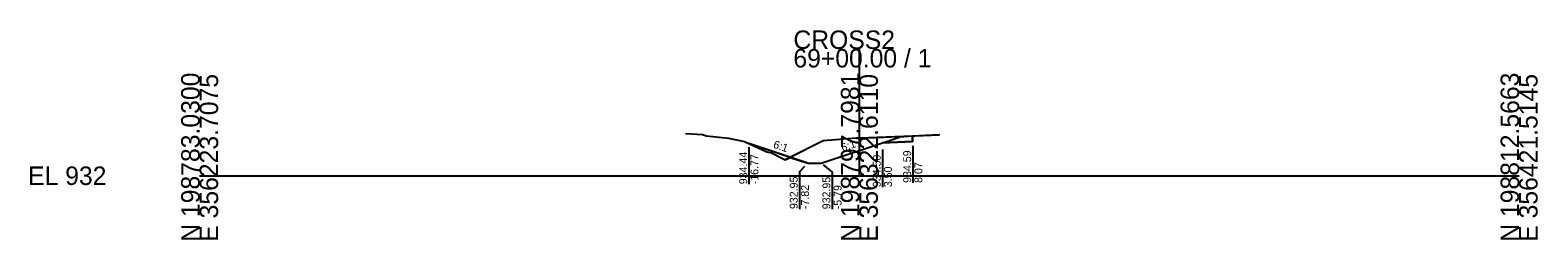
# Model space of a CAD drawing. Extents: x -26 to 203, y -10 to 14021.
# Drawn here: x -25.7 to 202.8, y 9990.3 to 10022 of the extents above; entities that cross this region are included whole.
import ezdxf

# ---------------------------------------------------------------- set-up
doc = ezdxf.new("R2010")
doc.units = 0
for name, color, linetype in [('Default', 7, 'Continuous'), ('P_E_XS_Ground', 7, 'Continuous'), ('P_XS', 7, 'Continuous'), ('P_XS_EAR_CommonGrnd', 7, 'Continuous'), ('P_XS_Lane', 7, 'Continuous'), ('P_XS_Rock', 7, 'Continuous')]:
    doc.layers.add(name, color=color, linetype=linetype)

msp = doc.modelspace()

# ---------------------------------------------------------------- linework, layer by layer
at = {"layer": 'Default'}
for p, q in [((100, 10000), (100, 10019.18)), ((0, 10000), (100, 10000)), ((100, 10000), (200, 10000))]:
    msp.add_line(p, q, dxfattribs=at)
at = {"layer": 'P_E_XS_Ground'}
for p, q in [((73.66, 10006.39), (76.24, 10006.23)), ((76.24, 10006.23), (76.83, 10006.06)), ((76.83, 10006.06), (80.18, 10005.68)), ((80.18, 10005.68), (82.58, 10005.19)), ((82.58, 10005.19), (85.98, 10003.6)), ((94.5, 10005.27), (88.77, 10002.41)), ((99.5, 10005.67), (94.5, 10005.27)), ((99.5, 10005.67), (100, 10005.69)), ((100, 10005.69), (112.07, 10006.17)), ((112.07, 10006.22), (112.13, 10006.22)), ((112.07, 10006.17), (112.07, 10006.22)), ((85.98, 10003.6), (86.67, 10003.46)), ((86.67, 10003.46), (88.77, 10002.41))]:
    msp.add_line(p, q, dxfattribs=at)
at = {"layer": 'P_XS'}
for p, q in [((103.5, 10005), (106.07, 10005.85)), ((108.07, 10006.01), (106.07, 10005.85)), ((112.07, 10006.17), (108.07, 10006.01))]:
    msp.add_line(p, q, dxfattribs=at)
at = {"layer": 'P_XS_EAR_CommonGrnd'}
for points in [[(94.21, 10001.9), (103.5, 10005), (108.07, 10005.18), (108.07, 10006.01), (100, 10005.69), (99.5, 10005.67), (94.5, 10005.27), (89.53, 10002.78), (92.18, 10001.9)], [(86.67, 10003.46), (88.77, 10002.41), (89.53, 10002.78), (83.23, 10004.88), (85.98, 10003.6)]]:
    msp.add_lwpolyline(points, close=True, dxfattribs=at)
at = {"layer": 'P_XS_Lane'}
for p, q in [((108.07, 10005.18), (103.5, 10005)), ((108.07, 10006.01), (108.07, 10005.18)), ((92.18, 10001.9), (83.23, 10004.88)), ((94.21, 10001.9), (103.5, 10005)), ((92.18, 10001.9), (94.21, 10001.9))]:
    msp.add_line(p, q, dxfattribs=at)
at = {"layer": 'P_XS_Rock'}
for p, q in [((83.24, 10004.3), (83.24, 9998.7)), ((103.48, 10003.96), (103.48, 9998.26)), ((108.09, 10004.52), (108.09, 9998.92)), ((90.9, 10000.57), (91.74, 10001.45)), ((94.53, 10001.63), (95.85, 10000.55)), ((90.9, 10000.57), (90.9, 9994.96)), ((95.85, 10000.55), (95.85, 9994.93))]:
    msp.add_line(p, q, dxfattribs=at)

# ---------------------------------------------------------------- texts
at = {"layer": 'Default'}
for s, p in [('CROSS2', (90, 10019.18)), ('69+00.00 / 1', (90, 10016.38)), ('EL 932', (-26, 9998.6))]:
    msp.add_text(s, height=2.8, dxfattribs=at).set_placement(p)
for s, p in [('N 198783.0300', (0, 9990)), ('E 356223.7075', (2.8, 9990)), ('N 198797.7981', (100, 9990)), ('E 356322.6110', (102.8, 9990)), ('N 198812.5663', (200, 9990)), ('E 356421.5145', (202.8, 9990))]:
    msp.add_text(s, height=2.8, rotation=90, dxfattribs=at).set_placement(p)
at = {"layer": 'P_XS_Rock'}
for s, rotation, p in [('6:1', 341.5651, (86.85, 10004.26)), ('6:1', 18.4349, (97.46, 10003.64)), ('934.44', 90, (82.99, 9998.71)), ('-16.77', 90, (84.69, 9998.71)), ('934.50', 90, (103.23, 9998.27)), ('934.59', 90, (107.84, 9998.92)), ('3.50', 90, (104.93, 9998.27)), ('8.07', 90, (109.54, 9998.92)), ('932.95', 90, (90.65, 9994.96)), ('-7.82', 90, (92.35, 9994.96)), ('932.95', 90, (95.6, 9994.93)), ('-5.79', 90, (97.3, 9994.93))]:
    msp.add_text(s, height=1.2, rotation=rotation, dxfattribs=at).set_placement(p)

doc.saveas('drawing.dxf')
